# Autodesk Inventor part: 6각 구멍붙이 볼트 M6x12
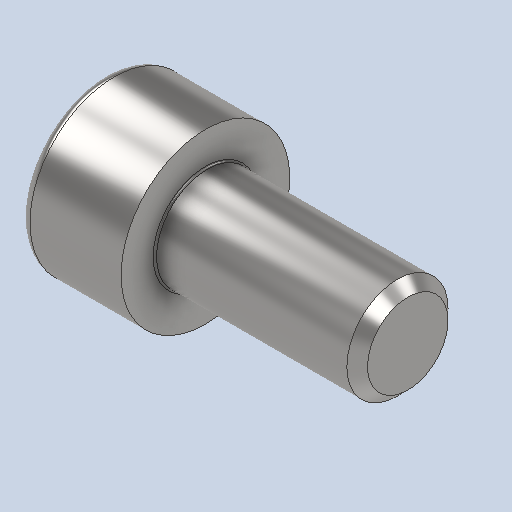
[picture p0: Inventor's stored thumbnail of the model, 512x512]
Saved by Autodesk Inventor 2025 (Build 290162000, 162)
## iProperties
Created: 2026-01
Part Number: 6각 구멍붙이 볼트 M6x12
Material: 강철, 연강
Description: 6각머리 태핑 나사
Document SubType Name: Modeling
Designer: KDI
Density: 7.85 g/cm^3
Appearance: 기본값
Author: jhkim
Sending System: Autodesk Inventor 2026
Preprocessor: ST-DEVELOPER v20.1
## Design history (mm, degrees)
feature "Solid1"
node "솔리드1"
